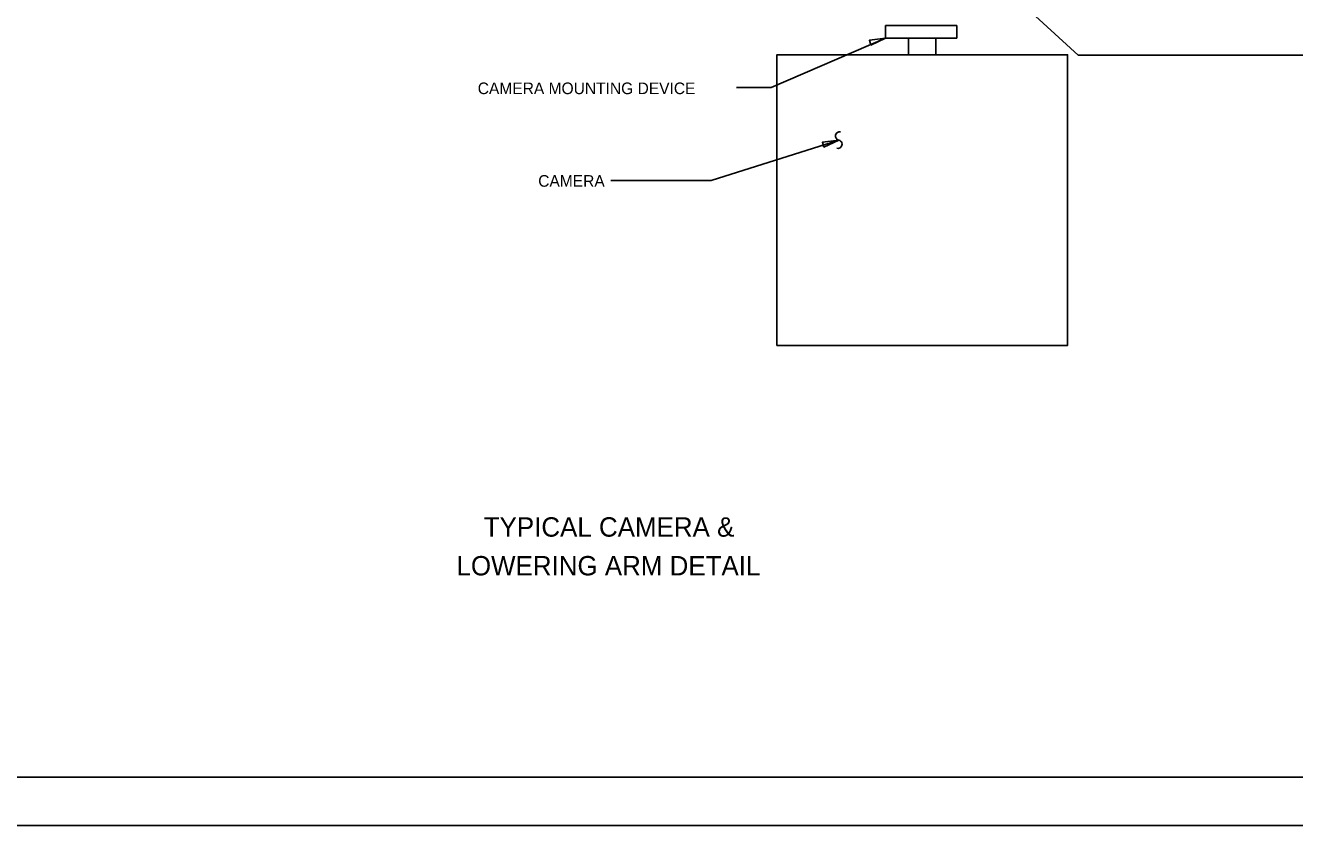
# Model space of a CAD drawing. Extents: x 1299104.6 to 1299141.4, y 239713.3 to 239735.3.
# Drawn here: x 1299115.78 to 1299128.87, y 239713.27 to 239721.53 of the extents above; entities that cross this region are included whole.
import ezdxf

# ---------------------------------------------------------------- set-up
doc = ezdxf.new("R2010")
doc.units = 0
for name, color, linetype in [('DIM TXT', 7, 'Continuous'), ('GS_plotshape_p', 7, 'Continuous'), ('Level 1', 7, 'Continuous'), ('Level 3', 7, 'Continuous'), ('Level 8', 7, 'Continuous')]:
    doc.layers.add(name, color=color, linetype=linetype)

msp = doc.modelspace()

# ---------------------------------------------------------------- linework, layer by layer
at = {"layer": 'GS_plotshape_p'}
msp.add_lwpolyline([(1299104.622, 239735.273), (1299138.622, 239735.273), (1299138.622, 239713.273), (1299104.622, 239713.273)], close=True, dxfattribs=at)
at = {"layer": 'Level 1'}
msp.add_lwpolyline([(1299138.122, 239713.773), (1299106.122, 239713.773), (1299106.122, 239734.773), (1299138.122, 239734.773)], close=True, dxfattribs=at)
at = {"layer": 'Level 3'}
for points in [[(1299124.653, 239721.532), (1299124.653, 239721.403), (1299125.387, 239721.403), (1299125.387, 239721.532)], [(1299124.89, 239721.403), (1299124.89, 239721.23), (1299125.171, 239721.23), (1299125.171, 239721.403)], [(1299123.531, 239718.23), (1299126.531, 239718.23), (1299126.531, 239721.23), (1299123.531, 239721.23)]]:
    msp.add_lwpolyline(points, close=True, dxfattribs=at)
at = {"layer": 'Level 8'}
for p, q in [((1299123.471, 239720.894), (1299124.653, 239721.403)), ((1299123.114, 239720.894), (1299123.471, 239720.894)), ((1299122.853, 239719.931), (1299124.169, 239720.349)), ((1299121.819, 239719.931), (1299122.853, 239719.931))]:
    msp.add_line(p, q, dxfattribs=at)
msp.add_lwpolyline([(1299124.999, 239722.731), (1299126.64, 239721.228), (1299132.049, 239721.228)], dxfattribs=at)
for points in [[(1299124.501, 239721.328), (1299124.485, 239721.38), (1299124.653, 239721.403)], [(1299124.017, 239720.275), (1299124.001, 239720.327), (1299124.169, 239720.349)]]:
    msp.add_lwpolyline(points, close=True, dxfattribs=at)
for centre, start, end in [((1299124.178, 239720.392), 77.6534, 257.6534), ((1299124.16, 239720.307), 257.6534, 77.6534)]:
    msp.add_arc(centre, 0.043, start, end, dxfattribs=at)

# ---------------------------------------------------------------- texts
at = {"layer": 'DIM TXT'}
for s, height, p in [('CAMERA MOUNTING DEVICE', 0.12, (1299120.444, 239720.824)), ('CAMERA', 0.12, (1299121.068, 239719.868)), ('TYPICAL CAMERA &', 0.2, (1299120.506, 239716.256)), ('LOWERING ARM DETAIL', 0.2, (1299120.225, 239715.856))]:
    msp.add_text(s, height=height, dxfattribs=at).set_placement(p)

doc.saveas('drawing.dxf')
